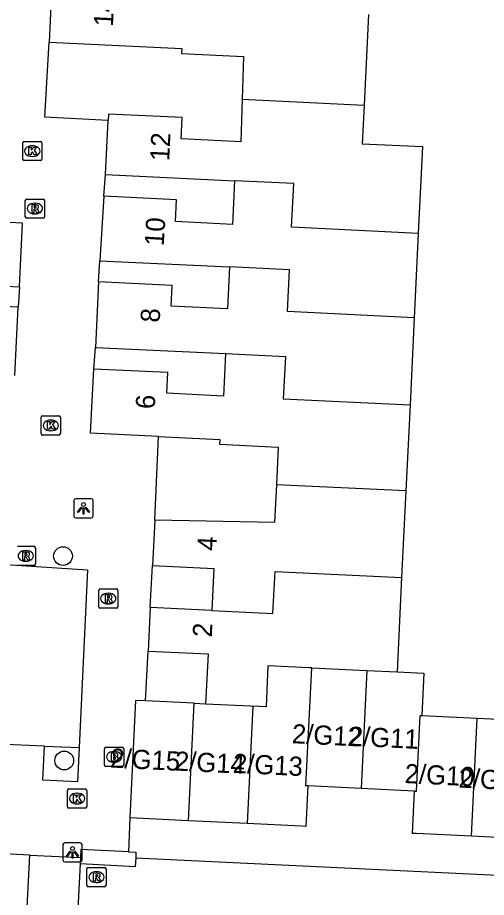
# Model space of a CAD drawing. Extents: x 162990 to 165007, y 383433 to 384336.
# Drawn here: x 164375.95 to 164400.4, y 383661.98 to 383707.84 of the extents above; entities that cross this region are included whole.
import ezdxf

# ---------------------------------------------------------------- set-up
doc = ezdxf.new("R2010")
doc.units = 0
for name, color, linetype in [('IMGEO_Boom', 7, 'Continuous'), ('IMGEO_Brandkraan', 7, 'Continuous'), ('IMGEO_Groenvoorziening', 7, 'Continuous'), ('IMGEO_Kolk', 7, 'Continuous'), ('IMGEO_Lichtpunt', 7, 'Continuous'), ('IMGEO_Pand', 7, 'Continuous'), ('IMGEO_Pand_nummerreeks', 7, 'Continuous'), ('IMGEO_Rijbaan_lokaal_open', 7, 'Continuous'), ('IMGEO_Rioolput', 7, 'Continuous'), ('IMGEO_Voetpad_open', 7, 'Continuous')]:
    doc.layers.add(name, color=color, linetype=linetype)

msp = doc.modelspace()

# ---------------------------------------------------------------- linework, layer by layer
at = {"layer": 'IMGEO_Boom'}
for centre in [(164378.322, 383679.771), (164378.387, 383669.116)]:
    msp.add_circle(centre, 0.489, dxfattribs=at)
at = {"layer": 'IMGEO_Brandkraan'}
for p, q in [((164380.486, 383668.878), (164380.486, 383669.73)), ((164380.561, 383669.804), (164381.413, 383669.804)), ((164380.974, 383669.584), (164380.999, 383669.584)), ((164381.487, 383669.73), (164381.487, 383668.878)), ((164381.413, 383668.804), (164380.561, 383668.804)), ((164380.997, 383669.024), (164380.972, 383669.024))]:
    msp.add_line(p, q, dxfattribs=at)
for points in [[(164380.486, 383668.878), (164380.486, 383669.73)], [(164380.561, 383669.804), (164381.413, 383669.804)], [(164381.487, 383669.73), (164381.487, 383668.878)], [(164380.834, 383669.504), (164380.834, 383669.104), (164381.047, 383669.104)], [(164381.065, 383669.504), (164380.834, 383669.504)], [(164381.013, 383669.423), (164380.959, 383669.423), (164380.959, 383669.347)], [(164380.959, 383669.347), (164381.012, 383669.347)], [(164381.021, 383669.271), (164380.959, 383669.271), (164380.959, 383669.19)], [(164380.959, 383669.19), (164381.021, 383669.19)], [(164381.413, 383668.804), (164380.561, 383668.804)]]:
    msp.add_lwpolyline(points, dxfattribs=at)
for centre, radius, start, end in [((164380.563, 383669.728), 0.0765, 91.552, 178.448), ((164380.563, 383669.728), 0.0765, 91.552, 178.448), ((164381.411, 383669.728), 0.0765, 1.552, 88.448), ((164381.411, 383669.728), 0.0765, 1.552, 88.448), ((164381.014, 383669.385), 0.0379, 267.8285, 90.9355), ((164381.022, 383669.23), 0.0404, 269.8759, 90.5077), ((164381.053, 383669.355), 0.251, 268.6676, 293.5347), ((164381.069, 383669.359), 0.145, 59.4692, 91.5367), ((164381.094, 383669.406), 0.0922, 285.5137, 58.1501), ((164381.099, 383669.214), 0.105, 301.3115, 78.989), ((164380.563, 383668.88), 0.0765, 181.552, 268.448), ((164380.563, 383668.88), 0.0765, 181.552, 268.448), ((164381.411, 383668.88), 0.0765, 271.552, 358.448), ((164381.411, 383668.88), 0.0765, 271.552, 358.448)]:
    msp.add_arc(centre, radius, start, end, dxfattribs=at)
for centre, major_axis, ratio, start_param, end_param in [((164380.973, 383669.304), (-0.387, 0.002), 0.722429, 4.712389, 7.853982), ((164380.998, 383669.304), (-0.39, 0.002), 0.717154, 1.570796, 4.712389)]:
    msp.add_ellipse(centre, major_axis=major_axis, ratio=ratio, start_param=start_param, end_param=end_param, dxfattribs=at)
at = {"layer": 'IMGEO_Groenvoorziening'}
msp.add_lwpolyline([(164377.359, 383669.864), (164379.158, 383669.795)], dxfattribs=at)
at = {"layer": 'IMGEO_Kolk'}
for p, q in [((164376.221, 383700.458), (164376.221, 383701.31)), ((164376.296, 383701.384), (164377.148, 383701.384)), ((164376.709, 383701.164), (164376.734, 383701.164)), ((164377.222, 383701.31), (164377.222, 383700.458)), ((164377.148, 383700.384), (164376.296, 383700.384)), ((164376.732, 383700.604), (164376.707, 383700.604)), ((164377.185, 383686.156), (164377.185, 383687.008)), ((164377.26, 383687.082), (164378.112, 383687.082)), ((164378.186, 383687.008), (164378.186, 383686.156)), ((164377.673, 383686.862), (164377.698, 383686.862)), ((164378.112, 383686.082), (164377.26, 383686.082)), ((164377.696, 383686.302), (164377.671, 383686.302)), ((164378.556, 383666.705), (164378.556, 383667.557)), ((164378.631, 383667.631), (164379.483, 383667.631)), ((164379.044, 383667.411), (164379.069, 383667.411)), ((164379.557, 383667.557), (164379.557, 383666.705)), ((164379.067, 383666.851), (164379.042, 383666.851)), ((164379.483, 383666.631), (164378.631, 383666.631))]:
    msp.add_line(p, q, dxfattribs=at)
for points in [[(164376.221, 383700.458), (164376.221, 383701.31)], [(164376.296, 383701.384), (164377.148, 383701.384)], [(164377.222, 383701.31), (164377.222, 383700.458)], [(164376.542, 383701.084), (164376.665, 383701.084), (164376.665, 383700.933), (164376.795, 383701.084), (164376.959, 383701.084), (164376.813, 383700.933), (164376.966, 383700.684), (164376.814, 383700.684), (164376.729, 383700.848), (164376.665, 383700.781), (164376.665, 383700.684), (164376.542, 383700.684), (164376.542, 383701.084)], [(164377.148, 383700.384), (164376.296, 383700.384)], [(164377.185, 383686.156), (164377.185, 383687.008)], [(164377.26, 383687.082), (164378.112, 383687.082)], [(164378.186, 383687.008), (164378.186, 383686.156)], [(164377.506, 383686.782), (164377.629, 383686.782), (164377.629, 383686.631), (164377.759, 383686.782), (164377.923, 383686.782), (164377.777, 383686.631), (164377.93, 383686.382), (164377.778, 383686.382), (164377.693, 383686.546), (164377.629, 383686.479), (164377.629, 383686.382), (164377.506, 383686.382), (164377.506, 383686.782)], [(164378.112, 383686.082), (164377.26, 383686.082)], [(164378.556, 383666.705), (164378.556, 383667.557)], [(164378.631, 383667.631), (164379.483, 383667.631)], [(164378.877, 383667.331), (164379, 383667.331), (164379, 383667.18), (164379.13, 383667.331), (164379.294, 383667.331), (164379.148, 383667.18), (164379.301, 383666.931), (164379.149, 383666.931), (164379.064, 383667.095), (164379, 383667.028), (164379, 383666.931), (164378.877, 383666.931), (164378.877, 383667.331)], [(164379.557, 383667.557), (164379.557, 383666.705)], [(164379.483, 383666.631), (164378.631, 383666.631)]]:
    msp.add_lwpolyline(points, dxfattribs=at)
for centre, start, end in [((164376.298, 383701.308), 91.552, 178.448), ((164376.298, 383701.308), 91.552, 178.448), ((164377.146, 383701.308), 1.552, 88.448), ((164377.146, 383701.308), 1.552, 88.448), ((164376.298, 383700.46), 181.552, 268.448), ((164376.298, 383700.46), 181.552, 268.448), ((164377.146, 383700.46), 271.552, 358.448), ((164377.146, 383700.46), 271.552, 358.448), ((164377.262, 383687.006), 91.552, 178.448), ((164377.262, 383687.006), 91.552, 178.448), ((164378.11, 383687.006), 1.552, 88.448), ((164378.11, 383687.006), 1.552, 88.448), ((164377.262, 383686.158), 181.552, 268.448), ((164377.262, 383686.158), 181.552, 268.448), ((164378.11, 383686.158), 271.552, 358.448), ((164378.11, 383686.158), 271.552, 358.448), ((164378.633, 383667.555), 91.552, 178.448), ((164378.633, 383667.555), 91.552, 178.448), ((164379.481, 383667.555), 1.552, 88.448), ((164379.481, 383667.555), 1.552, 88.448), ((164378.633, 383666.707), 181.552, 268.448), ((164378.633, 383666.707), 181.552, 268.448), ((164379.481, 383666.707), 271.552, 358.448), ((164379.481, 383666.707), 271.552, 358.448)]:
    msp.add_arc(centre, 0.0765, start, end, dxfattribs=at)
for centre, major_axis, ratio, start_param, end_param in [((164376.708, 383700.884), (-0.387, 0.002), 0.722429, 4.712389, 7.853982), ((164376.733, 383700.884), (-0.39, 0.002), 0.717154, 1.570796, 4.712389), ((164377.672, 383686.582), (-0.387, 0.002), 0.722429, 4.712389, 7.853982), ((164377.697, 383686.582), (-0.39, 0.002), 0.717154, 1.570796, 4.712389), ((164379.043, 383667.131), (-0.387, 0.002), 0.722429, 4.712389, 7.853982), ((164379.068, 383667.131), (-0.39, 0.002), 0.717154, 1.570796, 4.712389)]:
    msp.add_ellipse(centre, major_axis=major_axis, ratio=ratio, start_param=start_param, end_param=end_param, dxfattribs=at)
at = {"layer": 'IMGEO_Lichtpunt'}
for p, q in [((164378.892, 383682.663), (164378.892, 383681.856)), ((164378.892, 383682.663), (164378.892, 383681.856)), ((164379.794, 383682.758), (164378.986, 383682.758)), ((164379.794, 383682.758), (164378.986, 383682.758)), ((164379.888, 383681.856), (164379.888, 383682.663)), ((164379.888, 383681.856), (164379.888, 383682.663)), ((164378.986, 383681.762), (164379.794, 383681.762)), ((164378.986, 383681.762), (164379.794, 383681.762)), ((164378.319, 383664.729), (164378.319, 383663.922)), ((164378.319, 383664.729), (164378.319, 383663.922)), ((164379.221, 383664.824), (164378.413, 383664.824)), ((164379.221, 383664.824), (164378.413, 383664.824)), ((164379.315, 383663.922), (164379.315, 383664.729)), ((164379.315, 383663.922), (164379.315, 383664.729)), ((164378.413, 383663.828), (164379.221, 383663.828)), ((164378.413, 383663.828), (164379.221, 383663.828))]:
    msp.add_line(p, q, dxfattribs=at)
for points in [[(164379.266, 383682.327), (164379.305, 383682.299), (164379.117, 383682.037), (164379.079, 383682.064), (164379.266, 383682.327)], [(164379.368, 383682.279), (164379.415, 383682.279), (164379.415, 383681.957), (164379.368, 383681.957), (164379.368, 383682.279)], [(164379.478, 383682.299), (164379.516, 383682.326), (164379.703, 383682.064), (164379.664, 383682.036), (164379.478, 383682.299)], [(164378.693, 383664.393), (164378.732, 383664.365), (164378.544, 383664.103), (164378.506, 383664.13), (164378.693, 383664.393)], [(164378.795, 383664.345), (164378.842, 383664.345), (164378.842, 383664.023), (164378.795, 383664.023), (164378.795, 383664.345)], [(164378.905, 383664.365), (164378.943, 383664.392), (164379.13, 383664.13), (164379.091, 383664.102), (164378.905, 383664.365)]]:
    msp.add_lwpolyline(points, dxfattribs=at)
for centre in [(164379.391, 383682.461), (164378.818, 383664.527)]:
    msp.add_circle(centre, 0.0994, dxfattribs=at)
for centre, start, end in [((164378.986, 383682.663), 90, 180), ((164378.986, 383682.663), 90, 180), ((164379.794, 383682.663), 0, 90), ((164379.794, 383682.663), 0, 90), ((164378.986, 383681.856), 180, 270), ((164378.986, 383681.856), 180, 270), ((164379.794, 383681.856), 270, 0), ((164379.794, 383681.856), 270, 360), ((164378.413, 383664.729), 90, 180), ((164378.413, 383664.729), 90, 180), ((164379.221, 383664.729), 0, 90), ((164379.221, 383664.729), 0, 90), ((164378.413, 383663.922), 180, 270), ((164378.413, 383663.922), 180, 270), ((164379.221, 383663.922), 270, 0), ((164379.221, 383663.922), 270, 360)]:
    msp.add_arc(centre, 0.0946, start, end, dxfattribs=at)
at = {"layer": 'IMGEO_Pand'}
for points in [[(164377.765, 383709.944), (164377.601, 383706.556)], [(164394.247, 383708.01), (164394.018, 383703.281)], [(164377.601, 383706.556), (164384.514, 383706.222), (164384.501, 383705.964), (164387.729, 383705.808), (164387.665, 383703.588)], [(164387.665, 383703.588), (164387.6, 383701.367), (164384.48, 383701.518), (164384.534, 383702.63), (164380.692, 383702.815), (164380.676, 383702.481)], [(164387.665, 383703.588), (164394.018, 383703.281)], [(164394.018, 383703.281), (164393.921, 383701.267), (164397.065, 383701.115), (164396.846, 383696.586)], [(164380.54, 383699.657), (164380.676, 383702.481)], [(164387.262, 383699.333), (164387.152, 383697.062), (164384.187, 383697.205), (164384.242, 383698.341), (164380.448, 383698.525)], [(164380.54, 383699.657), (164387.262, 383699.333)], [(164396.846, 383696.586), (164390.244, 383696.909), (164390.354, 383699.188), (164387.262, 383699.333)], [(164380.448, 383698.525), (164380.236, 383695.168)], [(164376.049, 383693.813), (164376.21, 383697.125), (164373.104, 383697.276)], [(164396.846, 383696.586), (164396.634, 383692.198)], [(164369.165, 383693.075), (164369.273, 383695.278), (164372.179, 383695.136), (164372.124, 383694.004), (164376.049, 383693.813)], [(164386.997, 383694.84), (164386.892, 383692.664), (164383.969, 383692.805), (164384.021, 383693.877), (164380.18, 383694.063)], [(164380.236, 383695.168), (164386.997, 383694.84)], [(164396.634, 383692.198), (164390.031, 383692.515), (164390.136, 383694.687), (164386.997, 383694.84)], [(164380.18, 383694.063), (164380.015, 383690.65)], [(164375.976, 383692.744), (164369.165, 383693.075)], [(164375.803, 383689.179), (164375.976, 383692.744)], [(164396.634, 383692.198), (164396.415, 383687.652)], [(164380.015, 383690.65), (164386.793, 383690.323)], [(164386.793, 383690.323), (164386.686, 383688.114), (164383.743, 383688.256), (164383.795, 383689.333), (164379.924, 383689.52)], [(164386.793, 383690.323), (164389.919, 383690.176), (164389.81, 383687.967), (164396.415, 383687.652)], [(164383.303, 383686.008), (164379.763, 383686.179), (164379.924, 383689.52)], [(164396.415, 383687.652), (164396.198, 383683.164)], [(164383.303, 383686.008), (164386.502, 383685.853), (164386.49, 383685.604), (164389.542, 383685.456), (164389.447, 383683.49)], [(164389.447, 383683.49), (164389.352, 383681.526), (164383.109, 383681.648)], [(164396.198, 383683.164), (164389.447, 383683.49)], [(164396.198, 383683.164), (164395.98, 383678.65)], [(164383.109, 383681.648), (164382.995, 383679.281)], [(164382.995, 383679.281), (164386.188, 383679.127), (164386.082, 383676.939)], [(164386.082, 383676.939), (164389.271, 383676.786), (164389.377, 383678.97), (164395.98, 383678.65)], [(164395.98, 383678.65), (164395.742, 383673.73)], [(164382.87, 383677.094), (164382.761, 383674.821)], [(164386.082, 383676.939), (164382.87, 383677.094)], [(164382.761, 383674.821), (164385.884, 383674.67), (164385.758, 383672.069)], [(164391.291, 383673.938), (164391.164, 383673.944), (164389.007, 383674.045), (164388.908, 383671.92), (164388.218, 383671.953)], [(164391.085, 383667.79), (164390.981, 383667.795), (164391.291, 383673.938)], [(164391.291, 383673.938), (164394.15, 383673.804), (164394.168, 383673.803)], [(164394.168, 383673.803), (164393.871, 383667.656)], [(164394.168, 383673.803), (164395.742, 383673.73)], [(164395.742, 383673.73), (164397.131, 383673.665), (164397.025, 383671.456)], [(164382.623, 383672.22), (164382.095, 383672.246), (164381.799, 383666.119)], [(164385.157, 383672.098), (164382.623, 383672.22)], [(164384.86, 383665.971), (164385.157, 383672.098)], [(164385.157, 383672.098), (164385.758, 383672.069)], [(164385.758, 383672.069), (164388.072, 383671.96), (164388.218, 383671.953)], [(164388.218, 383671.953), (164387.922, 383665.823)], [(164396.657, 383667.521), (164396.752, 383667.516), (164396.952, 383671.46), (164397.025, 383671.456)], [(164397.025, 383671.456), (164399.924, 383671.316)], [(164399.627, 383665.169), (164399.924, 383671.316)], [(164399.924, 383671.316), (164402.484, 383671.192)], [(164391.085, 383667.79), (164390.983, 383665.675), (164390.765, 383665.686), (164387.922, 383665.823)], [(164393.871, 383667.656), (164391.085, 383667.79)], [(164396.657, 383667.521), (164393.871, 383667.656)], [(164399.627, 383665.169), (164396.728, 383665.309), (164396.662, 383665.312), (164396.551, 383665.318), (164396.657, 383667.521)], [(164384.86, 383665.971), (164381.799, 383666.119)], [(164387.922, 383665.823), (164384.86, 383665.971)], [(164402.702, 383665.021), (164399.627, 383665.169)], [(164376.586, 383664.182), (164374.59, 383664.279)], [(164376.42, 383660.795), (164376.586, 383664.182)]]:
    msp.add_lwpolyline(points, dxfattribs=at)
at = {"layer": 'IMGEO_Rijbaan_lokaal_open'}
for points in [[(164381.731, 383664.357), (164379.25, 383664.483), (164379.228, 383664.054)], [(164379.228, 383664.054), (164379.211, 383663.724)], [(164382.112, 383664.036), (164382.089, 383663.578), (164379.211, 383663.724)], [(164381.731, 383664.357), (164382.127, 383664.337), (164382.112, 383664.036)], [(164382.112, 383664.036), (164405.684, 383662.919)], [(164379.211, 383663.724), (164378.574, 383651.273)]]:
    msp.add_lwpolyline(points, dxfattribs=at)
at = {"layer": 'IMGEO_Rioolput'}
for p, q in [((164376.355, 383697.458), (164376.355, 383698.31)), ((164376.43, 383698.384), (164377.282, 383698.384)), ((164376.843, 383698.164), (164376.868, 383698.164)), ((164377.356, 383698.31), (164377.356, 383697.458)), ((164376.866, 383697.604), (164376.841, 383697.604)), ((164377.282, 383697.384), (164376.43, 383697.384)), ((164375.954, 383680.28), (164376.806, 383680.28)), ((164376.88, 383680.206), (164376.88, 383679.354)), ((164376.367, 383680.06), (164376.392, 383680.06)), ((164376.806, 383679.28), (164375.954, 383679.28)), ((164376.39, 383679.5), (164376.365, 383679.5)), ((164380.182, 383677.132), (164380.182, 383677.984)), ((164380.257, 383678.058), (164381.109, 383678.058)), ((164380.67, 383677.838), (164380.695, 383677.838)), ((164381.183, 383677.984), (164381.183, 383677.132)), ((164381.109, 383677.058), (164380.257, 383677.058)), ((164380.693, 383677.278), (164380.668, 383677.278)), ((164379.565, 383662.609), (164379.565, 383663.461)), ((164379.64, 383663.535), (164380.492, 383663.535)), ((164380.053, 383663.315), (164380.078, 383663.315)), ((164380.566, 383663.461), (164380.566, 383662.609)), ((164380.076, 383662.755), (164380.051, 383662.755)), ((164380.492, 383662.535), (164379.64, 383662.535))]:
    msp.add_line(p, q, dxfattribs=at)
for points in [[(164376.355, 383697.458), (164376.355, 383698.31)], [(164376.43, 383698.384), (164377.282, 383698.384)], [(164376.944, 383698.082), (164376.692, 383698.084), (164376.692, 383697.684)], [(164376.87, 383698.003), (164376.816, 383698.003), (164376.816, 383697.922)], [(164377.356, 383698.31), (164377.356, 383697.458)], [(164376.692, 383697.684), (164376.816, 383697.684), (164376.816, 383697.846), (164376.827, 383697.846)], [(164376.816, 383697.922), (164376.868, 383697.922)], [(164376.874, 383697.817), (164376.945, 383697.684), (164377.085, 383697.684), (164377.02, 383697.81)], [(164377.282, 383697.384), (164376.43, 383697.384)], [(164375.954, 383680.28), (164376.806, 383680.28)], [(164376.88, 383680.206), (164376.88, 383679.354)], [(164376.468, 383679.978), (164376.216, 383679.98), (164376.216, 383679.58)], [(164376.216, 383679.58), (164376.34, 383679.58), (164376.34, 383679.742), (164376.351, 383679.742)], [(164376.394, 383679.899), (164376.34, 383679.899), (164376.34, 383679.818)], [(164376.34, 383679.818), (164376.392, 383679.818)], [(164376.398, 383679.713), (164376.469, 383679.58), (164376.609, 383679.58), (164376.544, 383679.706)], [(164376.806, 383679.28), (164375.954, 383679.28)], [(164380.182, 383677.132), (164380.182, 383677.984)], [(164380.257, 383678.058), (164381.109, 383678.058)], [(164381.183, 383677.984), (164381.183, 383677.132)], [(164380.771, 383677.756), (164380.519, 383677.758), (164380.519, 383677.358)], [(164380.519, 383677.358), (164380.643, 383677.358), (164380.643, 383677.52), (164380.654, 383677.52)], [(164380.697, 383677.677), (164380.643, 383677.677), (164380.643, 383677.596)], [(164380.643, 383677.596), (164380.695, 383677.596)], [(164380.701, 383677.491), (164380.772, 383677.358), (164380.912, 383677.358), (164380.847, 383677.484)], [(164381.109, 383677.058), (164380.257, 383677.058)], [(164379.565, 383662.609), (164379.565, 383663.461)], [(164379.64, 383663.535), (164380.492, 383663.535)], [(164380.154, 383663.233), (164379.902, 383663.235), (164379.902, 383662.835)], [(164380.08, 383663.154), (164380.026, 383663.154), (164380.026, 383663.073)], [(164380.566, 383663.461), (164380.566, 383662.609)], [(164379.902, 383662.835), (164380.026, 383662.835), (164380.026, 383662.997), (164380.037, 383662.997)], [(164380.026, 383663.073), (164380.078, 383663.073)], [(164380.084, 383662.968), (164380.155, 383662.835), (164380.295, 383662.835), (164380.23, 383662.961)], [(164380.492, 383662.535), (164379.64, 383662.535)]]:
    msp.add_lwpolyline(points, dxfattribs=at)
for centre, radius, start, end in [((164376.432, 383698.308), 0.0765, 91.552, 178.448), ((164376.432, 383698.308), 0.0765, 91.552, 178.448), ((164376.876, 383697.907), 0.0964, 77.0061, 93.1865), ((164376.89, 383697.964), 0.0378, 276.6634, 79.6772), ((164376.943, 383697.972), 0.109, 350.3612, 89.416), ((164376.941, 383697.972), 0.112, 277.5842, 350.9817), ((164377.28, 383698.308), 0.0765, 1.552, 88.448), ((164377.28, 383698.308), 0.0765, 1.552, 88.448), ((164376.826, 383697.793), 0.0533, 26.0293, 88.6989), ((164376.852, 383698.111), 0.19, 274.7715, 282.9687), ((164376.925, 383697.757), 0.108, 29.5134, 73.7905), ((164376.432, 383697.46), 0.0765, 181.552, 268.448), ((164376.432, 383697.46), 0.0765, 181.552, 268.448), ((164377.28, 383697.46), 0.0765, 271.552, 358.448), ((164377.28, 383697.46), 0.0765, 271.552, 358.448), ((164376.804, 383680.204), 0.0765, 1.552, 88.448), ((164376.804, 383680.204), 0.0765, 1.552, 88.448), ((164376.35, 383679.689), 0.0533, 26.0293, 88.6989), ((164376.376, 383680.007), 0.19, 274.7715, 282.9687), ((164376.4, 383679.803), 0.0964, 77.0061, 93.1865), ((164376.414, 383679.86), 0.0378, 276.6634, 79.6772), ((164376.467, 383679.868), 0.109, 350.3612, 89.416), ((164376.465, 383679.868), 0.112, 277.5842, 350.9817), ((164376.449, 383679.653), 0.108, 29.5134, 73.7905), ((164376.804, 383679.356), 0.0765, 271.552, 358.448), ((164376.804, 383679.356), 0.0765, 271.552, 358.448), ((164380.259, 383677.982), 0.0765, 91.552, 178.448), ((164380.259, 383677.982), 0.0765, 91.552, 178.448), ((164381.107, 383677.982), 0.0765, 1.552, 88.448), ((164381.107, 383677.982), 0.0765, 1.552, 88.448), ((164380.653, 383677.467), 0.0533, 26.0293, 88.6989), ((164380.679, 383677.785), 0.19, 274.7715, 282.9687), ((164380.703, 383677.581), 0.0964, 77.0061, 93.1865), ((164380.717, 383677.638), 0.0378, 276.6634, 79.6772), ((164380.77, 383677.646), 0.109, 350.3612, 89.416), ((164380.768, 383677.646), 0.112, 277.5842, 350.9817), ((164380.752, 383677.431), 0.108, 29.5134, 73.7905), ((164380.259, 383677.134), 0.0765, 181.552, 268.448), ((164380.259, 383677.134), 0.0765, 181.552, 268.448), ((164381.107, 383677.134), 0.0765, 271.552, 358.448), ((164381.107, 383677.134), 0.0765, 271.552, 358.448), ((164379.642, 383663.459), 0.0765, 91.552, 178.448), ((164379.642, 383663.459), 0.0765, 91.552, 178.448), ((164380.086, 383663.058), 0.0964, 77.0061, 93.1865), ((164380.1, 383663.115), 0.0378, 276.6634, 79.6772), ((164380.153, 383663.123), 0.109, 350.3612, 89.416), ((164380.151, 383663.123), 0.112, 277.5842, 350.9817), ((164380.49, 383663.459), 0.0765, 1.552, 88.448), ((164380.49, 383663.459), 0.0765, 1.552, 88.448), ((164380.036, 383662.944), 0.0533, 26.0293, 88.6989), ((164380.062, 383663.262), 0.19, 274.7715, 282.9687), ((164380.135, 383662.908), 0.108, 29.5134, 73.7905), ((164379.642, 383662.611), 0.0765, 181.552, 268.448), ((164379.642, 383662.611), 0.0765, 181.552, 268.448), ((164380.49, 383662.611), 0.0765, 271.552, 358.448), ((164380.49, 383662.611), 0.0765, 271.552, 358.448)]:
    msp.add_arc(centre, radius, start, end, dxfattribs=at)
for centre, major_axis, ratio, start_param, end_param in [((164376.842, 383697.884), (-0.387, 0.002), 0.722429, 4.712389, 7.853982), ((164376.867, 383697.884), (-0.39, 0.002), 0.717154, 1.570796, 4.712389), ((164376.366, 383679.78), (-0.387, 0.002), 0.722429, 4.712389, 7.853982), ((164376.391, 383679.78), (-0.39, 0.002), 0.717154, 1.570796, 4.712389), ((164380.669, 383677.558), (-0.387, 0.002), 0.722429, 4.712389, 7.853982), ((164380.694, 383677.558), (-0.39, 0.002), 0.717154, 1.570796, 4.712389), ((164380.052, 383663.035), (-0.387, 0.002), 0.722429, 4.712389, 7.853982), ((164380.077, 383663.035), (-0.39, 0.002), 0.717154, 1.570796, 4.712389)]:
    msp.add_ellipse(centre, major_axis=major_axis, ratio=ratio, start_param=start_param, end_param=end_param, dxfattribs=at)
at = {"layer": 'IMGEO_Voetpad_open'}
for points in [[(164380.676, 383702.481), (164377.368, 383702.655), (164377.601, 383706.556)], [(164380.448, 383698.525), (164380.54, 383699.657)], [(164380.18, 383694.063), (164380.236, 383695.168)], [(164376.049, 383693.813), (164375.976, 383692.744)], [(164379.924, 383689.52), (164380.015, 383690.65)], [(164383.109, 383681.648), (164383.303, 383686.008)], [(164375.337, 383679.325), (164379.594, 383679.061), (164379.158, 383669.795)], [(164382.87, 383677.094), (164382.995, 383679.281)], [(164382.623, 383672.22), (164382.761, 383674.821)], [(164377.359, 383669.864), (164374.888, 383669.959)], [(164379.158, 383669.795), (164379.074, 383667.997), (164377.276, 383668.082), (164377.359, 383669.864)], [(164381.799, 383666.119), (164381.731, 383664.357)], [(164376.586, 383664.182), (164379.228, 383664.054)]]:
    msp.add_lwpolyline(points, dxfattribs=at)

# ---------------------------------------------------------------- texts
at = {"layer": 'IMGEO_Pand_nummerreeks'}
for s, rotation, p in [('14', 87.2287, (164380.924, 383707.357)), ('12', 87.2444, (164383.857, 383700.341)), ('10', 86.3865, (164383.569, 383695.91)), ('8', 87.2322, (164383.36, 383691.927)), ('6', 87.2411, (164383.106, 383687.417)), ('4', 87.2426, (164386.315, 383680.032)), ('2', 87.2557, (164386.078, 383675.524)), ('2/G12', 357.2212, (164390.241, 383670.018)), ('2/G11', 357.2212, (164393.203, 383669.893)), ('2/G15', 357.2186, (164380.765, 383668.751)), ('2/G14', 357.2186, (164384.14, 383668.594)), ('2/G13', 357.2212, (164387.164, 383668.476)), ('2/G10', 357.2212, (164396.12, 383667.942)), ('2/G09', 357.2186, (164398.928, 383667.709))]:
    msp.add_text(s, height=1, rotation=rotation, dxfattribs=at).set_placement(p)

doc.saveas('drawing.dxf')
